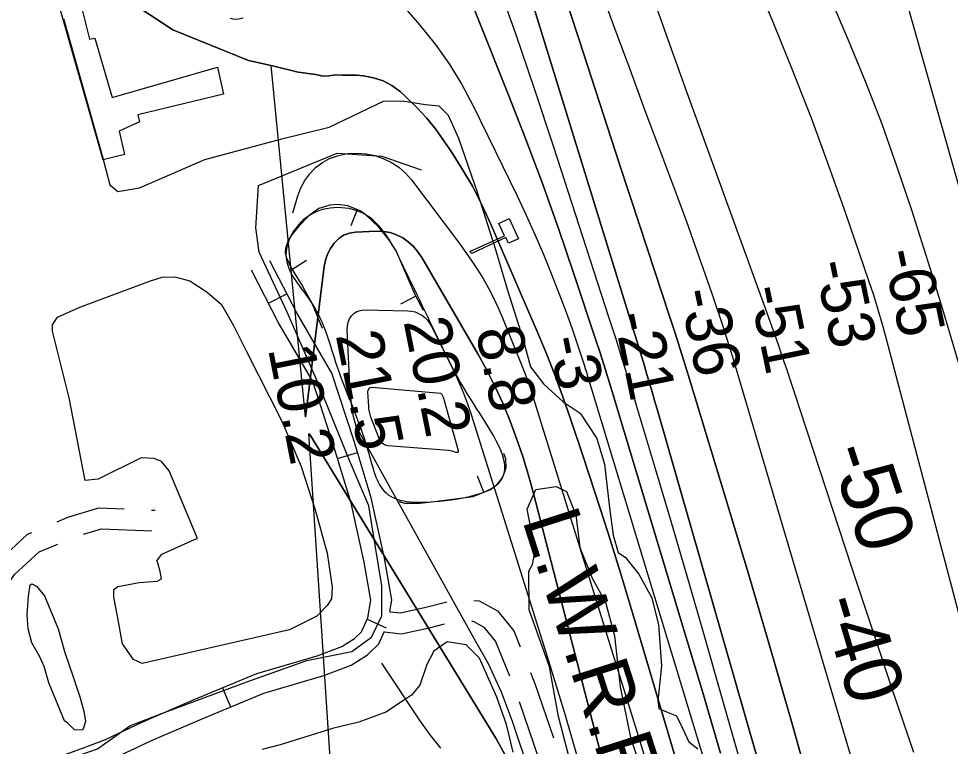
# Model space of a CAD drawing. Extents: x 3598634 to 3636690, y 517270 to 542944.
# Drawn here: x 3631009 to 3632357, y 526684 to 527737 of the extents above; entities that cross this region are included whole.
import ezdxf

# ---------------------------------------------------------------- set-up
doc = ezdxf.new("R2010")
doc.units = 0
for name, color, linetype in [('V-BORW-LINE', 7, 'Continuous'), ('V-CHAN-DOCK', 7, 'Continuous'), ('V-RIVR-EDGE', 7, 'Continuous'), ('V-RIVR-RANG', 7, 'Continuous'), ('V-ROAD-CNTR', 7, 'Continuous'), ('V-SITE-VEGE', 7, 'Continuous'), ('V-TOPO-DPTH', 7, 'Continuous'), ('V-TOPO-MAJR', 7, 'Continuous'), ('V-TOPO-MAJR-IDEN', 7, 'Continuous'), ('V-TOPO-MINR', 7, 'Continuous'), ('V-TOPO-MINR-IDEN', 7, 'Continuous'), ('V-TOPO-SHOR', 7, 'Continuous'), ('V-TOPO-WATR', 7, 'Continuous'), ('V-TOPO-WATR-IDEN', 7, 'Continuous')]:
    doc.layers.add(name, color=color, linetype=linetype)

msp = doc.modelspace()

# ---------------------------------------------------------------- linework, layer by layer
at = {"layer": 'V-BORW-LINE'}
for p, q in [((3631498.5, 527460.9), (3631489.1, 527437.7)), ((3631404.2, 527374.5), (3631425.3, 527387.9)), ((3631583.4, 527335.9), (3631561.3, 527324.3)), ((3631681.8, 527052), (3631672.8, 527075.3))]:
    msp.add_line(p, q, dxfattribs=at)
for points in [[(3631554.7, 527401.1), (3631546, 527415.9), (3631529.9, 527435.6), (3631511.4, 527453.1), (3631502.8, 527459.2), (3631484.9, 527466.4), (3631470.2, 527468.3), (3631459, 527467.6), (3631442.8, 527462.4), (3631428.4, 527451.9), (3631414.1, 527437.1), (3631404.7, 527425.9), (3631399.3, 527417.5), (3631394.6, 527404.9), (3631394.3, 527398.6), (3631395.6, 527392.3), (3631403.5, 527375.5), (3631419.4, 527350.4), (3631433.5, 527324.8), (3631447.8, 527289.6)], [(3631594.4, 527315), (3631582.4, 527337.7), (3631554.7, 527401.1)], [(3631559, 527038.7), (3631567.5, 527036.3), (3631589.3, 527036), (3631610.4, 527038.4), (3631666.2, 527045.9), (3631691.4, 527055.7), (3631701.6, 527063.4), (3631709.4, 527073.6), (3631714.1, 527087.6), (3631713.7, 527100.1), (3631710.8, 527108)]]:
    msp.add_lwpolyline(points, dxfattribs=at)
msp.add_spline([(3631554.7, 527401.1), (3631614.7, 527276.5), (3631661.4, 527188.7), (3631709.4, 527073.6), (3631610.4, 527038.4), (3631540.3, 527050.9), (3631514.1, 527112.2), (3631468.7, 527235.9), (3631433.5, 527324.8), (3631395.6, 527392.3), (3631428.4, 527451.9), (3631511.4, 527453.1), (3631554.7, 527401.1)], degree=3, dxfattribs=at)
at = {"layer": 'V-CHAN-DOCK'}
for points in [[(3631232.3, 527857.6), (3631246.6, 527795.2), (3631099.1, 527756), (3631111, 527707.5), (3631118.8, 527709.3), (3631144, 527623.4), (3631296.4, 527667.2), (3631305.2, 527628), (3631181.2, 527598.1), (3631183.5, 527587.9), (3631153.9, 527574.4), (3631161.8, 527540.5), (3631131.2, 527533.1), (3631062.5, 527773.5), (3631014.4, 527761.2), (3631013, 527766.1), (3631062.4, 527778.4), (3631057.8, 527816.8)], [(3631661.6, 527400.2), (3631711.5, 527423.2), (3631703.5, 527441), (3631718.6, 527447.9), (3631731.8, 527418.8), (3631717.5, 527412.3), (3631713.7, 527420.5), (3631664.3, 527397.6), (3631661.6, 527400.2)]]:
    msp.add_lwpolyline(points, dxfattribs=at)
at = {"layer": 'V-RIVR-EDGE'}
msp.add_lwpolyline([(3631073.5, 527737.5), (3631130, 527537.5), (3631140.7, 527496.6), (3631152.1, 527487), (3631183.4, 527492.3), (3631278.3, 527533.5), (3631389.4, 527563.2), (3631457.9, 527580.5), (3631536.7, 527618.1), (3631564.3, 527618.6), (3631597.3, 527613.1), (3631616.5, 527611.3), (3631630.3, 527597.5), (3631645.2, 527564.4), (3631672, 527486.3), (3631698.8, 527403.4), (3631716.1, 527344.5), (3631738.1, 527274.2), (3631749.4, 527233.4), (3631768, 527208.7), (3631796.7, 527182.8), (3631821.3, 527166.6), (3631845.2, 527129.9), (3631856.5, 527092.6), (3631863.6, 527029.6), (3631868.9, 526989.9), (3631876, 526964.7), (3631886.8, 526957.5), (3631906, 526933.4), (3631925.1, 526899.1), (3631934.6, 526860.1), (3631938.7, 526800.7), (3631933.7, 526749.6), (3631934.9, 526738.8), (3631946.3, 526734), (3631960.7, 526728.6), (3631969.1, 526710.5), (3631978.6, 526690.7), (3631991.2, 526680.5)], dxfattribs=at)
at = {"layer": 'V-ROAD-CNTR'}
for p, q in [((3631370.1, 527325.5), (3631396.8, 527339.2)), ((3631470.2, 527100.9), (3631498.9, 527109.5)), ((3631201.1, 527026.2), (3631206.4, 527026)), ((3631513, 526868.1), (3631540.3, 526855.6)), ((3631303.6, 526768.9), (3631315.1, 526741.2))]:
    msp.add_line(p, q, dxfattribs=at)
for points in [[(3630855.8, 526566.4), (3631067.5, 526661.3), (3631122.8, 526680.8), (3631169.6, 526714.1), (3631216.6, 526732.4), (3631340.3, 526778.3), (3631425.8, 526808.3), (3631490.7, 526821.7), (3631519.3, 526842.4), (3631534.2, 526873.1), (3631534.1, 526916.4), (3631524.5, 526975.4), (3631515.2, 527032.3), (3631487.6, 527098), (3631443.2, 527207.4), (3631397.2, 527312.7), (3631356.9, 527399.5), (3631352, 527434.8), (3631355.7, 527495.9), (3631469.8, 527542.5), (3631534.1, 527538.2), (3631591.3, 527518.5)], [(3631545.9, 526879.3), (3631548.5, 526895.7), (3631538.2, 526956.4), (3631518.8, 527043.8), (3631494.1, 527125.8), (3631462, 527224.4), (3631431.2, 527277.1), (3631411, 527311.6), (3631372.3, 527386.8)], [(3630967.6, 526636.4), (3631024.7, 526654.6), (3631082.9, 526674.7), (3631106.6, 526683.6), (3631134.2, 526694), (3631188.6, 526719.9), (3631262.6, 526751.8), (3631353.3, 526789.6), (3631440.8, 526815.4), (3631476.5, 526828.6), (3631494.7, 526840.3), (3631504.8, 526850.1), (3631514, 526870.3), (3631518.1, 526895.6), (3631508.8, 526950.6), (3631489.7, 527036.1), (3631465.4, 527116.8), (3631434.5, 527212.1), (3631405.3, 527261.9), (3631384.7, 527297.1), (3631345.6, 527373.1)], [(3631064.5, 527009.3), (3631079.8, 527015.7), (3631124.7, 527029.3), (3631161.2, 527027.9)], [(3630959.5, 526922.3), (3630979.8, 526952.7), (3631021.7, 526991.3), (3631027.7, 526993.8)], [(3631102.5, 526991.3), (3631128.5, 526999.2), (3631201.2, 526996.2)], [(3630990.2, 526914.3), (3631002.7, 526933.1), (3631038.2, 526965.6), (3631065.2, 526977)], [(3631545.9, 526879.1), (3631561.1, 526877.5), (3631597.7, 526885.5), (3631628.1, 526893.3)], [(3631667.5, 526895.3), (3631675, 526894.7), (3631701.5, 526880.1), (3631725, 526851.4), (3631734.4, 526828.1)], [(3631664.3, 526865.4), (3631666.3, 526865.3), (3631682, 526856.6), (3631698.9, 526836), (3631718.8, 526786.4)], [(3631537.6, 526849.8), (3631562.8, 526847.1), (3631604.7, 526856.3), (3631625, 526861.5)], [(3631134.3, 526662), (3631146, 526666.4), (3631201, 526692.6), (3631274.3, 526724.2), (3631363.3, 526761.2), (3631450.2, 526786.9), (3631490, 526801.5), (3631513.6, 526816.7), (3631529.7, 526832.5), (3631538, 526850.7)], [(3631749.3, 526791), (3631756.3, 526773.5), (3631782.4, 526696.6)], [(3631732.9, 526749), (3631761.2, 526665.7), (3631764.3, 526654)]]:
    msp.add_lwpolyline(points, dxfattribs=at)
at = {"layer": 'V-SITE-VEGE'}
msp.add_lwpolyline([(3631811.9, 526642.2), (3631789.8, 526727.3), (3631776.7, 526799.2), (3631747.3, 526882), (3631747, 526937.5), (3631752, 526947.2), (3631756.3, 526967.6), (3631744.6, 527027.3), (3631757.1, 527055.7), (3631786.5, 527060.3), (3631801.2, 527052.8), (3631814.7, 527019.2), (3631820.8, 526971.8), (3631838.3, 526927.6), (3631857.6, 526893.1), (3631871, 526844), (3631879.2, 526770.5), (3631894, 526696.9), (3631917.8, 526626.5)], dxfattribs=at)
msp.add_lwpolyline([(3631074.8, 526721.3), (3631052.2, 526775.9), (3631045.8, 526799.9), (3631039.4, 526813.9), (3631028, 526833.8), (3631022.4, 526854.5), (3631021, 526874.3), (3631022.9, 526901.5), (3631025.5, 526918), (3631028, 526919.6), (3631034.6, 526916.2), (3631046, 526902.1), (3631066.1, 526854.1), (3631075.7, 526820.2), (3631087.7, 526784.6), (3631097.3, 526755.7), (3631102.9, 526735), (3631105.3, 526720.1), (3631102.7, 526711.1), (3631101, 526707.8), (3631089.5, 526707.9), (3631079.7, 526717.9)], close=True, dxfattribs=at)
at = {"layer": 'V-TOPO-DPTH'}
for points in [[(3631686.1, 527974.3), (3631902.6, 527272.7), (3631906.4, 527260.2), (3631910.3, 527247.6), (3631914.1, 527235.1), (3631917.8, 527222.5), (3631921.5, 527209.9), (3631925.2, 527197.4), (3631928.9, 527184.8), (3631932.5, 527172.2), (3632155.4, 526395.7)], [(3632155.4, 526395.7), (3631932.5, 527172.2), (3631928.9, 527184.8), (3631925.2, 527197.4), (3631921.5, 527209.9), (3631917.8, 527222.5), (3631914.1, 527235.1), (3631910.3, 527247.6), (3631906.4, 527260.2), (3631902.6, 527272.7), (3631686.1, 527974.3)], [(3632024.3, 526674.4), (3631998, 526763.7), (3631971.4, 526852.9), (3631867, 527199.3), (3631861.3, 527217.9), (3631855.5, 527236.6), (3631849.5, 527255.1), (3631843.4, 527273.7), (3631812.1, 527368.1), (3631789.8, 527433.6), (3631766.6, 527498.9), (3631742.3, 527563.7), (3631717.2, 527628.2), (3631629.3, 527848.4)], [(3631629.3, 527848.4), (3631717.2, 527628.2), (3631742.3, 527563.7), (3631766.6, 527498.9), (3631789.8, 527433.6), (3631812.1, 527368.1), (3631843.4, 527273.7), (3631849.5, 527255.1), (3631855.5, 527236.6), (3631861.3, 527217.9), (3631867, 527199.3), (3631971.4, 526852.9), (3631998, 526763.7), (3632024.3, 526674.4)], [(3631790.9, 527794.7), (3631820, 527705.4), (3631849.1, 527616.1), (3631878.3, 527526.8), (3631907.6, 527437.5), (3631950, 527308), (3631958, 527283.5), (3631965.9, 527258.8), (3631973.6, 527234.2), (3631981.2, 527209.5), (3632032.1, 527042.4), (3632064.6, 526934), (3632096.7, 526825.4), (3632127.9, 526716.6), (3632158.5, 526607.7)], [(3632158.5, 526607.7), (3632127.9, 526716.6), (3632096.7, 526825.4), (3632064.6, 526934), (3632032.1, 527042.4), (3631981.2, 527209.5), (3631973.6, 527234.2), (3631965.9, 527258.8), (3631958, 527283.5), (3631950, 527308), (3631907.6, 527437.5), (3631878.3, 527526.8), (3631849.1, 527616.1), (3631820, 527705.4), (3631790.9, 527794.7)], [(3631846.1, 527791.4), (3631869.4, 527727.6), (3631892.8, 527664), (3631916.4, 527600.4), (3631940.1, 527536.8), (3631962.4, 527477.5), (3631975, 527443.6), (3631987.3, 527409.6), (3631999.3, 527375.4), (3632011, 527341.2), (3632027.4, 527292.5), (3632030.6, 527282.5), (3632033.9, 527272.6), (3632036.9, 527262.6), (3632040, 527252.6), (3632237.5, 526586)], [(3631846.1, 527791.4), (3631869.4, 527727.6), (3631892.8, 527664), (3631916.4, 527600.4), (3631940.1, 527536.8), (3631962.4, 527477.5), (3631975, 527443.6), (3631987.3, 527409.6), (3631999.3, 527375.4), (3632011, 527341.2), (3632027.4, 527292.5), (3632030.6, 527282.5), (3632033.9, 527272.6), (3632036.9, 527262.6), (3632040, 527252.6), (3632237.5, 526586)], [(3632047.1, 526370.7), (3631896.9, 526877.4), (3631879.4, 526935.2), (3631861.5, 526992.9), (3631843.1, 527050.5), (3631824.2, 527107.9), (3631807.4, 527158.2), (3631796.3, 527190.2), (3631784.6, 527222), (3631772.1, 527253.6), (3631759, 527284.8), (3631691.5, 527440.9), (3631678.9, 527468.1), (3631665.2, 527494.7), (3631650.1, 527520.6), (3631634.1, 527545.9), (3631624, 527560.7), (3631611.7, 527577.7), (3631598.6, 527594), (3631584.3, 527609.3), (3631569.3, 527623.9), (3631560.6, 527631.7), (3631548.7, 527640.5), (3631536, 527647.5), (3631522.2, 527651.9), (3631507.7, 527654.6), (3631497.6, 527655.3), (3631487.5, 527655.7), (3631477.3, 527655.6), (3631467.5, 527656), (3631457.4, 527654.5), (3631448.9, 527653.9), (3631438.7, 527656.3), (3631413.1, 527660.1), (3631374.1, 527669.5), (3631341.3, 527676.6), (3631231.7, 527721.3), (3631164.1, 527766.2)], [(3631374.1, 527669.5), (3631413.1, 527660.1), (3631438.7, 527656.3), (3631448.9, 527653.9), (3631457.4, 527654.5), (3631467.5, 527656), (3631477.3, 527655.6), (3631487.5, 527655.7), (3631497.6, 527655.3), (3631507.7, 527654.6), (3631522.2, 527651.9), (3631536, 527647.5), (3631548.7, 527640.5), (3631560.6, 527631.7), (3631569.3, 527623.9), (3631584.3, 527609.3), (3631598.6, 527594), (3631611.7, 527577.7), (3631624, 527560.7), (3631634.1, 527545.9), (3631650.1, 527520.6), (3631665.2, 527494.7), (3631678.9, 527468.1), (3631691.5, 527440.9), (3631759, 527284.8), (3631772.1, 527253.6), (3631784.6, 527222), (3631796.3, 527190.2), (3631807.4, 527158.2), (3631824.2, 527107.9), (3631843.1, 527050.5), (3631861.5, 526992.9), (3631879.4, 526935.2), (3631896.9, 526877.4), (3632047.1, 526370.7)], [(3631940.1, 526327.3), (3631753, 527052), (3631745.8, 527078.1), (3631738, 527103.9), (3631729.2, 527129.5), (3631719.9, 527154.9), (3631709.6, 527179.8), (3631698.4, 527204.4), (3631686.2, 527228.4), (3631673.2, 527252.1), (3631592.1, 527391.5), (3631586.4, 527399.8), (3631580, 527407.5), (3631572.5, 527414.1), (3631564.4, 527420.1), (3631555.4, 527424.6), (3631546.1, 527427.9), (3631536.4, 527429.5), (3631526.4, 527430), (3631496.2, 527428.5), (3631487.2, 527426.8), (3631478.9, 527423.8), (3631471.6, 527418.8), (3631465, 527412.5), (3631459.8, 527404.6), (3631455.5, 527396.4), (3631452.6, 527387.6), (3631450.7, 527378.4), (3631423.8, 527160.6), (3631374.1, 527669.5)], [(3631587.6, 526105.5), (3631500.1, 526094.4), (3631495, 526142.9), (3631494, 526152.6), (3631493.2, 526162.4), (3631492.4, 526172.1), (3631491.7, 526181.9), (3631488.1, 526234.2), (3631428.4, 527136.9)], [(3631428.4, 527136.9), (3631428.6, 527136.8), (3631429.4, 527136.1), (3631429.9, 527135.3), (3631699.3, 526695.9), (3631716.5, 526664.7)]]:
    msp.add_lwpolyline(points, dxfattribs=at)
at = {"layer": 'V-TOPO-MAJR'}
msp.add_lwpolyline([(3631920.9, 527783.6), (3631948.2, 527707), (3631975.7, 527630.5), (3632087, 527323.8), (3632093.8, 527304.9), (3632100.5, 527286), (3632107.1, 527267), (3632113.6, 527248), (3632120, 527228.9), (3632126.4, 527209.9), (3632132.7, 527190.8), (3632139, 527171.7), (3632185.6, 527029.1), (3632214.7, 526940.6), (3632244.1, 526852.2), (3632273.8, 526763.8), (3632303.6, 526675.6)], dxfattribs=at)
at = {"layer": 'V-TOPO-MINR'}
for points in [[(3632388.1, 527428.7), (3632181.1, 528160.5)], [(3631686.1, 527974.3), (3631902.6, 527272.7), (3631906.4, 527260.2), (3631910.3, 527247.6), (3631914.1, 527235.1), (3631917.8, 527222.5), (3631921.5, 527209.9), (3631925.2, 527197.4), (3631928.9, 527184.8), (3631932.5, 527172.2), (3632155.4, 526395.7)], [(3632043.7, 527867.4), (3632100.9, 527730.2), (3632128.5, 527662.1), (3632155.3, 527593.8), (3632180.6, 527524.9), (3632205.1, 527455.7), (3632238.5, 527358.4), (3632245.4, 527337.5), (3632252, 527316.5), (3632258.2, 527295.4), (3632264, 527274.1), (3632439.6, 526608.5)], [(3631629.3, 527848.4), (3631717.2, 527628.2), (3631742.3, 527563.7), (3631766.6, 527498.9), (3631789.8, 527433.6), (3631812.1, 527368.1), (3631843.4, 527273.7), (3631849.5, 527255.1), (3631855.5, 527236.6), (3631861.3, 527217.9), (3631867, 527199.3), (3631971.4, 526852.9), (3631998, 526763.7), (3632024.3, 526674.4)], [(3631698.5, 527797), (3631727.4, 527716), (3631755.3, 527634.7), (3631782.3, 527553.1), (3631862.4, 527305.7), (3631872.6, 527273.9), (3631882.6, 527242), (3631892.5, 527210.1), (3631902.2, 527178.1), (3631929.6, 527086.5), (3631952.7, 527008.7), (3631975.6, 526930.8), (3631998.2, 526852.8), (3632020.6, 526774.7), (3632134, 526375.6)], [(3631790.9, 527794.7), (3631820, 527705.4), (3631849.1, 527616.1), (3631878.3, 527526.8), (3631907.6, 527437.5), (3631950, 527308), (3631958, 527283.5), (3631965.9, 527258.8), (3631973.6, 527234.2), (3631981.2, 527209.5), (3632032.1, 527042.4), (3632064.6, 526934), (3632096.7, 526825.4), (3632127.9, 526716.6), (3632158.5, 526607.7)], [(3631846.1, 527791.4), (3631869.4, 527727.6), (3631892.8, 527664), (3631916.4, 527600.4), (3631940.1, 527536.8), (3631962.4, 527477.5), (3631975, 527443.6), (3631987.3, 527409.6), (3631999.3, 527375.4), (3632011, 527341.2), (3632027.4, 527292.5), (3632030.6, 527282.5), (3632033.9, 527272.6), (3632036.9, 527262.6), (3632040, 527252.6), (3632237.5, 526586)], [(3631553.8, 527769.1), (3631589.4, 527727.8), (3631611.3, 527700.3), (3631631.7, 527671.8), (3631649.8, 527641.9), (3631666.5, 527610.9), (3631729.8, 527481), (3631743.2, 527452.7), (3631756.2, 527424.1), (3631768.5, 527395.2), (3631780.3, 527366.1), (3631788.5, 527345.1), (3631795.7, 527326.3), (3631802.7, 527307.4), (3631809.4, 527288.5), (3631815.9, 527269.4), (3631825, 527241.9), (3631826.8, 527236.5), (3631828.5, 527231.1), (3631830.2, 527225.7), (3631831.9, 527220.3), (3632054.8, 526485.1)], [(3632182.8, 527767.8), (3632208.5, 527707.8), (3632233.6, 527646.7), (3632257.5, 527585.2), (3632279.6, 527523), (3632300.5, 527460.4), (3632330.3, 527366.3), (3632335.3, 527350.4), (3632340.2, 527334.4), (3632345.1, 527318.3), (3632349.9, 527302.3), (3632495, 526809.4), (3632513.5, 526746.6), (3632532, 526683.9)], [(3631314.6, 527738.1), (3631320.7, 527736.8), (3631327, 527737.1), (3631333.4, 527738.6)], [(3631405.2, 527456.4), (3631412.6, 527481.1), (3631417.1, 527492.6), (3631422.7, 527503.3), (3631430, 527512.9), (3631438.4, 527521.9), (3631448.2, 527529.2), (3631458.6, 527535.1), (3631469.9, 527539), (3631481.9, 527541.6), (3631485.4, 527542), (3631498.4, 527542.5), (3631511.3, 527541.8), (3631523.9, 527539.1), (3631536.3, 527535.1), (3631548, 527529.2), (3631558.8, 527522.2), (3631568.3, 527513.6), (3631577, 527503.9), (3631645.1, 527413.8), (3631654.5, 527400.9), (3631663.6, 527387.9), (3631672.2, 527374.6), (3631680.6, 527361.1), (3631688.5, 527347.3), (3631695.9, 527333.2), (3631702.6, 527318.9), (3631708.9, 527304.3), (3631735.4, 527238.9), (3631740.2, 527226.6), (3631744.8, 527214.2), (3631749.1, 527201.7), (3631753.2, 527189.1), (3631895, 526732), (3631917.4, 526658.8)], [(3631423.8, 527160.6), (3631450.7, 527378.4), (3631452.6, 527387.6), (3631455.5, 527396.4), (3631459.8, 527404.6), (3631465, 527412.5), (3631471.6, 527418.8), (3631478.9, 527423.8), (3631487.2, 527426.8), (3631496.2, 527428.5), (3631526.4, 527430), (3631536.4, 527429.5), (3631546.1, 527427.9), (3631555.4, 527424.6), (3631564.4, 527420.1), (3631572.5, 527414.1), (3631580, 527407.5), (3631586.4, 527399.8), (3631592.1, 527391.5), (3631673.2, 527252.1), (3631686.2, 527228.4), (3631698.4, 527204.4), (3631709.6, 527179.8), (3631719.9, 527154.9), (3631729.2, 527129.5), (3631738, 527103.9), (3631745.8, 527078.1), (3631753, 527052), (3631940.1, 526327.3)], [(3631854.7, 526327.5), (3631723.5, 526720.3), (3631707.2, 526762.5), (3631688.5, 526803.5), (3631666.2, 526842.6), (3631497, 527147.3), (3631492.8, 527163.5), (3631490.2, 527180), (3631488.6, 527196.7), (3631484.1, 527287.6), (3631484.4, 527292.9), (3631485.4, 527298), (3631487.5, 527302.8), (3631490.3, 527307.3), (3631494, 527310.9), (3631498.2, 527313.6), (3631502.9, 527315.1), (3631508.1, 527315.8), (3631571.8, 527314.6), (3631577.2, 527314), (3631582.4, 527312.8)], [(3631582.4, 527312.8), (3631587.3, 527310.8), (3631592, 527308.1), (3631596.3, 527304.7), (3631600.1, 527301), (3631603.3, 527296.6), (3631606.1, 527292), (3631639.1, 527225.4), (3631646, 527210.5), (3631652.5, 527195.4), (3631658.2, 527180), (3631663.5, 527164.5), (3631771.4, 526820.6), (3631799.3, 526729.1), (3631826.2, 526637.2)], [(3631619.6, 527195.1), (3631620.6, 527194.3), (3631622.5, 527190.3), (3631623.2, 527188.3), (3631644.7, 527112.3), (3631644.5, 527110.7), (3631643.9, 527109.7), (3631642.8, 527109.3), (3631641.2, 527109.4), (3631638.7, 527110.5), (3631636.1, 527111.5), (3631633.4, 527112), (3631630.6, 527112.4), (3631542.9, 527119.1), (3631538.8, 527120.1), (3631535.2, 527122.4), (3631533.6, 527124), (3631531.2, 527127.5), (3631530.3, 527129.5), (3631518.4, 527160.6), (3631517.2, 527164.3), (3631516.2, 527168.2), (3631515.6, 527172), (3631515.2, 527176), (3631514.1, 527197.4), (3631514.5, 527199.8), (3631516.5, 527202.9), (3631517.5, 527203.5), (3631519.8, 527203.9), (3631619.1, 527195.2), (3631619.6, 527195.1)], [(3631716.5, 526664.7), (3631699.3, 526695.9), (3631429.9, 527135.3), (3631429.4, 527136.1), (3631428.6, 527136.8), (3631428.4, 527136.9)], [(3631619.6, 526681.5), (3631604.1, 526700.9), (3631589.6, 526721.2), (3631534.3, 526804.8)]]:
    msp.add_lwpolyline(points, dxfattribs=at)
at = {"layer": 'V-TOPO-SHOR'}
for points in [[(3631105.1, 527068.7), (3631082, 527188.4), (3631057.8, 527284.9), (3631057.6, 527294.2), (3631065, 527305.2), (3631097, 527319.9), (3631199.4, 527358), (3631216.2, 527363.1), (3631234.7, 527363.6), (3631256.4, 527358), (3631281.5, 527341.7), (3631302, 527323.7), (3631319.8, 527293.3), (3631337.7, 527256.8), (3631389.7, 527154.8), (3631417.7, 527089.2), (3631437.8, 527026.5), (3631454.9, 526963.8), (3631462.3, 526914.6), (3631461.2, 526897.6), (3631455.3, 526888.2), (3631440.3, 526872.4), (3631400.7, 526852.8), (3631187.6, 526804.1), (3631175.1, 526809.9), (3631159.1, 526832.6), (3631151.9, 526872.5), (3631146.6, 526900.2), (3631146.3, 526911), (3631152.3, 526915.7), (3631183, 526921.2), (3631209.2, 526923.4), (3631215.3, 526926.6), (3631213.5, 526937.4), (3631210, 526949.6), (3631208.4, 526952.7), (3631215.9, 526962.1), (3631234.2, 526970.3), (3631263.1, 526983.4), (3631267.7, 526985.1), (3631226.6, 527082.7), (3631215.5, 527096.3), (3631204.6, 527100.6), (3631186, 527101.7), (3631123.6, 527070.8), (3631105.1, 527068.7)], [(3631724.3, 526675.6), (3631714.4, 526715.9), (3631700.5, 526755.6), (3631675.7, 526811.6), (3631656.4, 526831.3), (3631628.6, 526835.4), (3631609.6, 526822), (3631599.1, 526802.6), (3631589.1, 526772.9), (3631577.2, 526758.1), (3631566.8, 526751.7)], [(3631566.8, 526751.7), (3631540, 526733.8), (3631501, 526719.2), (3631462.6, 526709.9), (3631422.9, 526697.3), (3631387.1, 526686.6), (3631361.1, 526679.7)]]:
    msp.add_lwpolyline(points, dxfattribs=at)
at = {"layer": 'V-TOPO-WATR'}
msp.add_lwpolyline([(3631164.1, 527766.2), (3631231.7, 527721.3), (3631341.3, 527676.6), (3631374.1, 527669.5), (3631413.1, 527660.1), (3631438.7, 527656.3), (3631448.9, 527653.9), (3631457.4, 527654.5), (3631467.5, 527656), (3631477.3, 527655.6), (3631487.5, 527655.7), (3631497.6, 527655.3), (3631507.7, 527654.6), (3631522.2, 527651.9), (3631536, 527647.5), (3631548.7, 527640.5), (3631560.6, 527631.7), (3631569.3, 527623.9), (3631584.3, 527609.3), (3631598.6, 527594), (3631611.7, 527577.7), (3631624, 527560.7), (3631634.1, 527545.9), (3631650.1, 527520.6), (3631665.2, 527494.7), (3631678.9, 527468.1), (3631691.5, 527440.9), (3631759, 527284.8), (3631772.1, 527253.6), (3631784.6, 527222), (3631796.3, 527190.2), (3631807.4, 527158.2), (3631824.2, 527107.9), (3631843.1, 527050.5), (3631861.5, 526992.9), (3631879.4, 526935.2), (3631896.9, 526877.4), (3632047.1, 526370.7)], dxfattribs=at)

# ---------------------------------------------------------------- texts
at = {"layer": 'V-RIVR-RANG'}
for s, rotation, p in [('-65', 281.5468, (3632258.8, 527399.4)), ('-53', 281.5468, (3632160, 527383.2)), ('-36', 281.5468, (3631964.3, 527342.1)), ('-51', 281.5468, (3632065.4, 527346.7)), ('-21', 281.5468, (3631869.2, 527308.2)), ('20.2', 281.2683, (3631565.4, 527299.2)), ('21.5', 281.2683, (3631467.3, 527279.5)), ('8.8', 281.2683, (3631669.9, 527286.4)), ('-3', 281.5468, (3631774.1, 527273.7)), ('10.2', 281.2683, (3631369.3, 527259.7))]:
    msp.add_text(s, height=67, rotation=rotation, dxfattribs=at).set_placement(p)
at = {"layer": 'V-TOPO-MAJR-IDEN'}
msp.add_text('-50', height=83, rotation=288.217, dxfattribs=at).set_placement((3632180.4, 527111.3))
at = {"layer": 'V-TOPO-MINR-IDEN'}
msp.add_text('-40', height=83, rotation=286.507, dxfattribs=at).set_placement((3632168, 526893.5))
at = {"layer": 'V-TOPO-WATR-IDEN'}
msp.add_text('L.W.R.P.', height=83, rotation=287.7902, dxfattribs=at).set_placement((3631736.8, 527012.2))

doc.saveas('drawing.dxf')
